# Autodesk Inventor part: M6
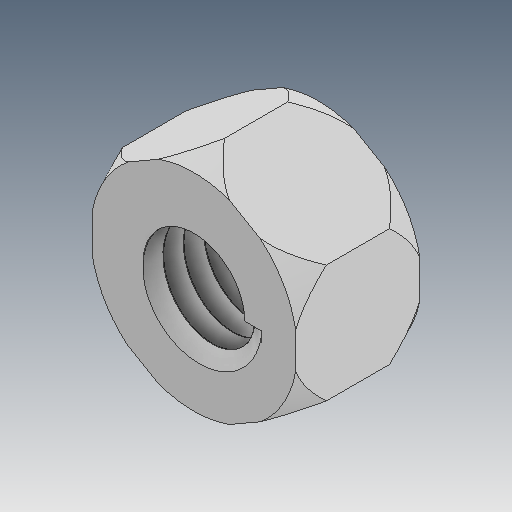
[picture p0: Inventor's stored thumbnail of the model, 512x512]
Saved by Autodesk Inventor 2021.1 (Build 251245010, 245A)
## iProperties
Created: 2019-05
Part Number: M6
Material: Ogólny
Document SubType Name: Modeling
Designer: user
Density: 1 g/cm^3
Appearance: Domyślna
Author: user
Revision Number: ÈÎºÎ
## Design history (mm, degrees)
feature "ÊäÈë1"
node "Bryła1"
